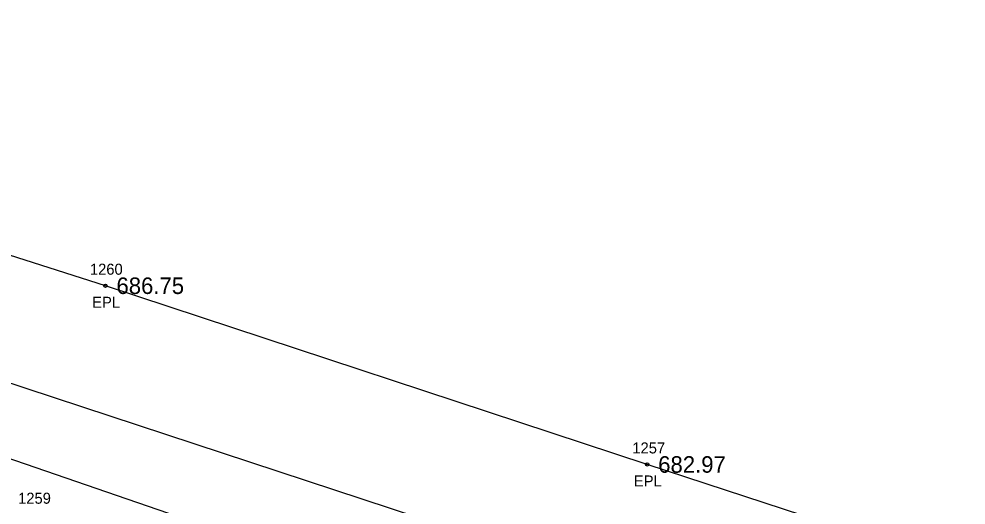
# Model space of a CAD drawing. Extents: x 1655137 to 1657928, y 1003994 to 1005407.
# Drawn here: x 1655939.3 to 1656025.3, y 1004758.8 to 1004802.9 of the extents above; entities that cross this region are included whole.
import ezdxf

# ---------------------------------------------------------------- set-up
doc = ezdxf.new("R2010")
doc.units = 0
for name, color, linetype in [('RD_EX_Misc', 7, 'Continuous'), ('RD_EX_Road', 7, 'Continuous'), ('RD_EX_Road_txCode', 7, 'Continuous'), ('RD_EX_TX_Road_ELEV', 7, 'Continuous'), ('RD_HC_Cl', 7, 'Continuous'), ('RD_SMD_Locator', 7, 'Continuous')]:
    doc.layers.add(name, color=color, linetype=linetype)

msp = doc.modelspace()

# ---------------------------------------------------------------- linework, layer by layer
at = {"layer": 'RD_EX_Misc'}
msp.add_lwpolyline([(1655875.572, 1004783.81), (1655899.124, 1004775.727), (1655924.143, 1004767.915), (1655957.486, 1004756.441), (1655982.243, 1004748.48), (1656011.779, 1004739.501), (1656033.158, 1004732.174), (1656057.837, 1004724.625), (1656091.047, 1004714.315), (1656106.296, 1004710.837), (1656119.065, 1004707.85), (1656127.527, 1004711.026), (1656137.413, 1004709.544), (1656150.275, 1004705.031), (1656164.334, 1004699.598), (1656171.578, 1004694.85), (1656180.966, 1004693.871), (1656197.975, 1004688.492), (1656215.111, 1004682.576), (1656240.683, 1004675.392), (1656271.878, 1004665.005), (1656304.44, 1004655.084)], dxfattribs=at)
at = {"layer": 'RD_EX_Road'}
msp.add_lwpolyline([(1656365.125, 1004639.993), (1656336.036, 1004649.337), (1656302.553, 1004660.365), (1656279.148, 1004668.232), (1656240.072, 1004681.052), (1656188.234, 1004698.028), (1656166.718, 1004705.508), (1656141.162, 1004714.063), (1656093.113, 1004730.113), (1656044.163, 1004746.75), (1655996.355, 1004762.445), (1655947.197, 1004778.676), (1655899.09, 1004794.03), (1655850.622, 1004809.986), (1655801.911, 1004826.095), (1655753.093, 1004842.312), (1655704.246, 1004858.105)], dxfattribs=at)
at = {"layer": 'RD_HC_Cl'}
msp.add_line((1655701.505, 1004847.777), (1656069.258, 1004726.842), dxfattribs=at)
at = {"layer": 'RD_SMD_Locator'}
for centre in [(1655947.197, 1004778.676), (1655996.355, 1004762.445)]:
    msp.add_circle(centre, 0.15, dxfattribs=at)

# ---------------------------------------------------------------- texts
at = {"layer": 'RD_EX_Road_txCode'}
for s, p in [('1260', (1655945.788, 1004779.676)), ('EPL', (1655945.992, 1004776.676)), ('1257', (1655995.009, 1004763.445)), ('EPL', (1655995.15, 1004760.445)), ('1259', (1655939.271, 1004758.879))]:
    msp.add_text(s, height=1, dxfattribs=at).set_placement(p)
at = {"layer": 'RD_EX_TX_Road_ELEV'}
for s, p in [('686.75', (1655948.197, 1004777.926)), ('682.97', (1655997.355, 1004761.695))]:
    msp.add_text(s, height=1.5, dxfattribs=at).set_placement(p)

doc.saveas('drawing.dxf')
